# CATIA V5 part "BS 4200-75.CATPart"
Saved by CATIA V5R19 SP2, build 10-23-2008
Part number: BS 4200-75
Bounding box of the stored display mesh (mm): x -47.487 to 47.487, y -47.487 to 47.487, z 0 to 215
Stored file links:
  C:\Users\Bora\Desktop\3D Katı model\BS serisi\BS 4200\BS 4200-75.CATPart
  C:\Program Files\Dassault Systemes\B19\intel_a\reffiles\standard\MetricThickPitch.txt
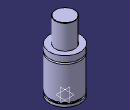
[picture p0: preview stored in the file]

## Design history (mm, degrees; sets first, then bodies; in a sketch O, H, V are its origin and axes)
Body1 (main body)
  Sketch1 on yz-plane, origin (0, 0, 0), H (0, 1, 0), V (0, 0, 1)
    point P2 (47.5, 115.5)
    point P5 (30, 214)
    point P7 (30, 214)
    point P11 (47.5, 120.5)
    point P13 (47.5, 120.5)
    point P14 (47.5, 115.5)
    line L1 (47.5, 13) -> (47.5, 115.5)
    line L2 (44.5, 13) -> (44.5, 8)
    line L3 (30, 214) -> (30, 139)
    arc A1 centre (29, 214) radius 1 from (30, 214) to (29, 215) ccw
    line L4 (47.5, 0) -> (47.5, 8)
    line L5 (47.5, 120.5) -> (47.5, 139)
    arc A2 centre (47.5, 118) radius 2.5 from (47.5, 120.5) to (47.5, 115.5) ccw
    line L6 (29, 215) -> (0, 215)
    point P15 (0, 215)
    line L7 (30, 139) -> (47.5, 139)
    line L8 (0, 0) -> (47.5, 0)
    line L9 (44.5, 13) -> (47.5, 13)
    line L10 (44.5, 8) -> (47.5, 8)
    coincidence: P15 V, P2 P14, P5 P7, P11 P13
    tangency: L6 A1
    horizontal: L7 H, L8 H, L9 H, L10 H
  Shaft1: profile Sketch1, axis Sketch1.V, angle 360
  Sketch2 on face of Shaft1 from Sketch1.L8, origin (0, 0, 0), H (1, 0, 0), V (0, -1, 0)
    point P1 (30, 0)
    distance P1 V = 30
  Hole1: placed by Sketch2, at (30, 0, 0) direction (0, 0, 1), diameter 6.647, depth 7, threaded "M8", thread diameter 8, thread depth 7, pitch 1.25
  CircPattern1: of Hole1, instances 4, angular step 90, axis from xy-plane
